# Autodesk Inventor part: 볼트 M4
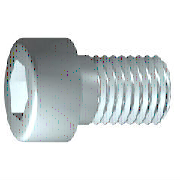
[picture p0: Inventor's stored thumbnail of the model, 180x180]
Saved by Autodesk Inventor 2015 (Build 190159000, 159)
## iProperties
IsCustomPart: 0
Created: 2012-02
Part Number: 볼트 M4
Material: 스테인리스강
Description: 6각 소켓 머리 캡 나사
Document SubType Name: Modeling
Standard: ISO 4762
Designer: mduedu
Standard Revision: Fourth edition 2004-03-01
Standards Organization: ISO
Language: ko-KR
Size Designation: M4 x 12
Categories: <MemberInstance><Categories><Category DisplayName="조임쇠" InternalName="e4da775c-781d-43d5-af7c-5136215cf5a6" Mnemonic="FSTN"><Category DisplayName="볼트" InternalN
Density: 8.08 g/cm^3
Appearance: 반광택
Author: mduedu
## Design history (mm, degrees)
sketch "스케치1"
  geometry: L1 (-1, 0)-(12, 0); L2 (12, 0)-(12, 2); L3 (12, 2)-(1.75, 2); L4 (1.75, 2)-(1.32, 2); L5 (1.32, 2)-(0, 2); L6 (0, 2)-(0, 3.5); L7 (0, 3.5)-(-4, 3.5); L8 (-4, 3.5)-(-4, 1.732); L9 (-4, 1.732)-(-2, 1.732); L10 (-2, 1.732)-(-1, 0); L11 (-7.2, 0)-(15.2, 0) reference; L12 (0, -0.7)-(0, 4.2) reference; L13 (1.75, 2)-(0, 2)
  constraints: 22 end point, 6 parallel, 2 collinear, 2 perpendicular, 1 horizontal, 1 point on line
  dimensions: "d1" = 10.25 distance from line of L3.end L2 (= GEL); "d2" = 0.42952 distance of L4.end L3.end (computed from GAL); "d3" = 4 distance between parallel lines of L8 L6 (= KOH); "d4" = 2 distance of L8.end L9.end (= INTI); "d5" = 60 deg angle of L10 L1; "d6" = 4 diameter of L3 L1 (= GD); "d7" = 4 diameter of L5 L1 (= BDM); "d8" = 3.4641 diameter of L9 L1 (= 1.1547 x SW); "d9" = 7 diameter of L7 L1 (= KOD); "d26" = 12 distance between parallel lines of L12 L2 (= NLG)
revolve "본체" sketch "스케치1" stored, may be unused: angle "d10" = 90 deg
sketch "스케치2"
  geometry: L1 (0, -4.9)-(0, 4.9) reference; L2 (-4.9, 0)-(4.9, 0) reference; L3 (1.732, 0)-(0.866, -1.5); L4 (0.866, -1.5)-(-0.866, -1.5); L5 (-0.866, -1.5)-(-1.732, 0); L6 (-1.732, 0)-(-0.866, 1.5); L7 (-0.866, 1.5)-(0.866, 1.5); L8 (0.866, 1.5)-(1.732, 0); 2 further points
  constraints: 12 end point, 1 coincident, 1 horizontal alignment, 1 point on line, 12 other
extrude "슬롯" join sketch "스케치2" stored distance "d11" = 10; taper "d12" = 0 deg
workplane "Work Plane1"
fillet "Fillet2" dims "d30" = 0.1 (= R)
body "Solid1"
fillet "모깎기1" dims "d17" = 0.4 (= RR)
feature "스레드" dims "d13" = 10.25 (= GEL), "d14" = 0
chamfer "모따기1" distance "d15" = 0.42941 (= -0.5 x SPD + 0.5 x GD); stored, may be unused: second distance "d16" = 0.42941 (= GUL), angle "d27" = 45 deg
other parameters: "GD" = 4 [user parameter; used in 2 equation terms], "NLG" = 12 [user parameter; used in 1 equation term], "GEL" = 10.25 [user parameter; used in 2 equation terms], "KOD" = 7 [user parameter; used in 1 equation term], "KOH" = 4 [user parameter; used in 1 equation term], "INTI" = 2 [user parameter; used in 1 equation term], "GAL" = 0.42941 (= 0.61345 x PTC) [user parameter; used in 1 equation term], "GUL" = 0.42941 (= 0.61345 x PTC) [user parameter; used in 1 equation term], "BDM" = 4 (= NND) [user parameter; used in 1 equation term], "SW" = 3 [user parameter; used in 2 equation terms], "RR" = 0.4 [user parameter; used in 1 equation term], "SPD" = 3.14117 (= NND - 1.2269 x PTC) [user parameter; used in 1 equation term], "d19" = 0, "d28" = 0, "d29" = 0, "R" = 0.1 [user parameter; used in 1 equation term], "TOA" = 30 deg [user parameter], "GD1" = 3.14117 (= THREADDIA - 1.2269 x PTC) [user parameter], "THREADDIA" = 4 [user parameter; used in 1 equation term], "FAWI" = 45 deg [user parameter], "TPU" = 14.28571 (computed from PTC) [user parameter], "PTC" = 0.7 [user parameter; used in 5 equation terms], "NND" = 4 [user parameter; used in 2 equation terms], "E0" = 3.465 (= 1.155 x SW) [user parameter]
